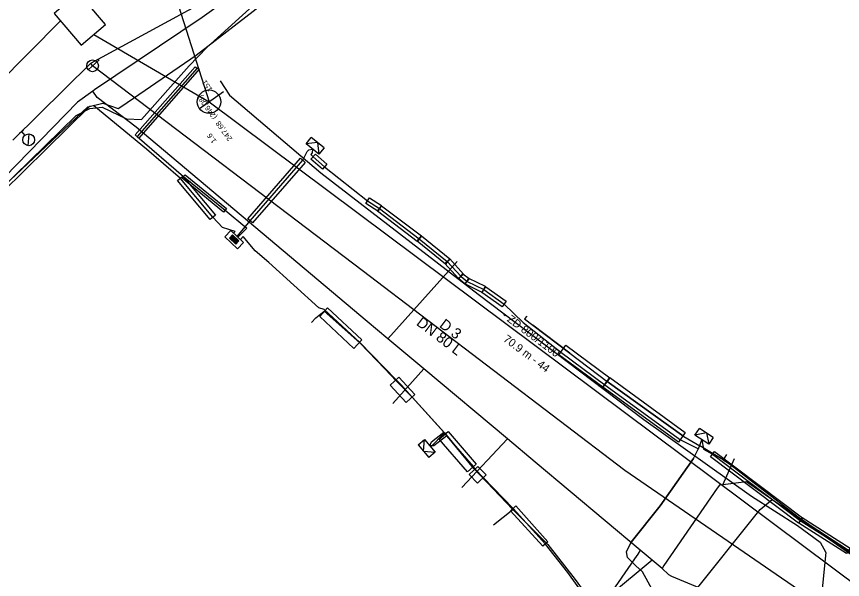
# Model space of a CAD drawing. Extents: x -600636 to -600148, y -1203980 to -1203569.
# Drawn here: x -600384.3 to -600313.9, y -1203678.1 to -1203630.1 of the extents above; entities that cross this region are included whole.
import ezdxf

# ---------------------------------------------------------------- set-up
doc = ezdxf.new("R2010")
doc.units = 0
for name, color, linetype in [('Cetin zam průběh', 7, 'Continuous'), ('EON objekty', 7, 'Continuous'), ('EON podzemní NN', 7, 'Continuous'), ('EON podzemní VN', 7, 'Continuous'), ('GasNet NTL', 7, 'Continuous'), ('Implicitní', 7, 'Continuous'), ('VaK Břeclav_kanalizace', 7, 'Continuous'), ('Vak Břeclav_vodovod', 7, 'Continuous'), ('Vrstva 9', 7, 'Continuous')]:
    doc.layers.add(name, color=color, linetype=linetype)

# ---------------------------------------------------------------- blocks, each defined once
blk = doc.blocks.new('NN630')
at = {"layer": 'Vrstva 9'}
for points in [[(-0.003, -0.7), (-0.703, 0)], [(-0.703, -0.7), (-0.703, 0), (0.697, 0), (0.697, -0.7)], [(-0.703, -0.7), (0.697, -0.7)], [(-0.003, -0.7), (0.697, 0)]]:
    blk.add_lwpolyline(points, dxfattribs=at)
blk = doc.blocks.new('NN620')
at = {"layer": 'EON objekty'}
for points in [[(0.752, 0.004), (-0.748, 0.004)], [(-0.748, 0.004), (-0.748, -0.746)], [(0.752, -0.746), (0.752, 0.004)], [(0.368, -0.18), (-0.376, -0.18)], [(-0.376, -0.18), (-0.376, -0.558)], [(-0.376, -0.558), (0.368, -0.558)], [(0.321, -0.227), (-0.329, -0.227)], [(-0.329, -0.227), (-0.329, -0.51)], [(-0.329, -0.51), (0.321, -0.51)], [(0.274, -0.274), (-0.281, -0.274)], [(-0.281, -0.274), (-0.281, -0.463)], [(-0.281, -0.463), (0.274, -0.463)], [(0.227, -0.321), (-0.234, -0.321)], [(-0.234, -0.321), (-0.234, -0.416)], [(-0.234, -0.416), (0.227, -0.416)], [(-0.193, -0.369), (0.185, -0.369)], [(0.227, -0.416), (0.227, -0.321)], [(0.274, -0.463), (0.274, -0.274)], [(0.321, -0.51), (0.321, -0.227)], [(0.368, -0.558), (0.368, -0.18)], [(-0.748, -0.746), (0.752, -0.746)]]:
    blk.add_lwpolyline(points, dxfattribs=at)
blk = doc.blocks.new('MoSymbol 2')
at = {"layer": 'Implicitní'}
blk.add_line((0, 0.0005), (0, -0.00075), dxfattribs=at)
blk.add_circle((0, 0), 0.0005, dxfattribs=at)
blk = doc.blocks.new('MoSymbol 3')
at = {"layer": 'Implicitní'}
for p, q in [((-0.000225, 0.00095), (0.000225, 0.00095)), ((0, 0.00095), (0, 0.0005)), ((-0.000365, -0.000365), (0.000365, 0.000365))]:
    blk.add_line(p, q, dxfattribs=at)
blk.add_circle((0, 0), 0.0005, dxfattribs=at)

msp = doc.modelspace()

# ---------------------------------------------------------------- linework, layer by layer
at = {"layer": 'Cetin zam průběh'}
for points in [[(-600403.75, -1203662.4), (-600400.59, -1203659.29), (-600391.04, -1203649.83), (-600378.25, -1203637.79), (-600376.97, -1203637.47), (-600375.66, -1203637.95), (-600375.36, -1203637.74), (-600369.01, -1203633.38), (-600361.52, -1203627.61), (-600348.82, -1203618.06), (-600335.53, -1203608.82), (-600318.11, -1203596.27), (-600313.64, -1203592.14)], [(-600368.09, -1203632.74), (-600363.25, -1203628.32)], [(-600385.87, -1203644.99), (-600379.24, -1203638.53), (-600378.07, -1203637.95), (-600377.04, -1203637.82), (-600374.96, -1203638.83), (-600373.66, -1203638.86), (-600369.62, -1203634.3), (-600368.09, -1203632.74)], [(-600375.36, -1203637.74), (-600369.01, -1203633.38)], [(-600373.66, -1203638.86), (-600369.62, -1203634.3)], [(-600359.16, -1203656.16), (-600358.81, -1203655.77), (-600358.09, -1203655.2), (-600355.04, -1203657.89), (-600352.93, -1203660.11), (-600351.96, -1203661.13), (-600350.57, -1203662.57), (-600347.84, -1203665.57)], [(-600358.09, -1203655.2), (-600355.04, -1203657.89)], [(-600340.82, -1203655.62), (-600341, -1203655.85), (-600340.3, -1203656.39), (-600337.13, -1203658.78), (-600333.94, -1203661.19), (-600327.42, -1203665.89), (-600326.06, -1203666.68)], [(-600337.13, -1203658.78), (-600340.3, -1203656.39)], [(-600351.96, -1203661.13), (-600350.57, -1203662.57)], [(-600327.42, -1203665.89), (-600333.94, -1203661.19)], [(-600349.03, -1203666.79), (-600347.84, -1203665.57)], [(-600347.84, -1203665.57), (-600345.32, -1203668.62)], [(-600341.99, -1203672.1), (-600345.32, -1203668.62), (-600347.84, -1203665.57)], [(-600331.52, -1203676.9), (-600332.22, -1203676.19), (-600332.3, -1203675.71), (-600331.92, -1203674.9), (-600329.44, -1203671.78), (-600326.6, -1203667.76), (-600326.06, -1203666.68)], [(-600324.05, -1203667.87), (-600326.06, -1203666.68)], [(-600323.77, -1203667.42), (-600324.05, -1203667.87)], [(-600326.6, -1203667.76), (-600329.44, -1203671.78), (-600331.92, -1203674.9)], [(-600324.05, -1203667.87), (-600323.52, -1203668.21), (-600317.28, -1203673.02), (-600311.48, -1203676.78)], [(-600323.52, -1203668.21), (-600317.28, -1203673.02)], [(-600329.02, -1203689.27), (-600327.65, -1203686.16), (-600327.07, -1203683.69), (-600326.94, -1203681.95), (-600327.13, -1203680.22), (-600326.9, -1203679.6), (-600320.9, -1203672.11), (-600319.87, -1203671.25), (-600312.14, -1203676.45), (-600307.68, -1203679.27), (-600299.7, -1203684.11), (-600292.77, -1203688.32), (-600284.45, -1203693.32), (-600273.46, -1203699.98), (-600262.73, -1203706.4), (-600257.97, -1203709.2), (-600243.31, -1203717.93), (-600240.56, -1203720.13), (-600238.73, -1203718.32)], [(-600343.64, -1203673.42), (-600341.99, -1203672.1)], [(-600341.99, -1203672.1), (-600339.02, -1203675.1)], [(-600341.99, -1203672.1), (-600339.02, -1203675.1), (-600336.67, -1203678.06), (-600335.49, -1203679.73), (-600334.6, -1203680.94), (-600332.38, -1203684.29), (-600330.34, -1203687.27), (-600329.66, -1203687.89)], [(-600329.66, -1203687.89), (-600329.92, -1203686.15), (-600329.28, -1203683.93), (-600328.92, -1203681.87), (-600329, -1203680.95), (-600330.94, -1203677.41), (-600331.52, -1203676.9)]]:
    msp.add_lwpolyline(points, dxfattribs=at)
at = {"layer": 'EON podzemní NN'}
for points in [[(-600369.107, -1203634.396), (-600368.748, -1203634.595), (-600368.748, -1203634.595), (-600373.899, -1203640.453), (-600374.2, -1203640.188)], [(-600359.216, -1203642.251), (-600358.833, -1203641.82), (-600357.859, -1203642.686), (-600358.243, -1203643.117)], [(-600360.118, -1203642.173), (-600359.712, -1203642.525), (-600364.197, -1203647.69), (-600364.6, -1203647.341)], [(-600370.59, -1203644.082), (-600370.152, -1203643.715), (-600367.372, -1203647.024), (-600367.812, -1203647.394)], [(-600369.954, -1203643.575), (-600366.423, -1203646.455), (-600366.676, -1203646.765), (-600370.207, -1203643.885)], [(-600354.533, -1203646.022), (-600354.217, -1203645.538), (-600353.207, -1203646.198), (-600353.522, -1203646.681)], [(-600353.548, -1203646.691), (-600353.191, -1203646.221), (-600349.803, -1203648.791), (-600350.16, -1203649.261)], [(-600350.151, -1203649.253), (-600349.786, -1203648.798), (-600347.372, -1203650.733), (-600347.738, -1203651.189)], [(-600347.794, -1203651.139), (-600347.366, -1203650.751), (-600346.195, -1203652.04), (-600346.624, -1203652.43)], [(-600346.606, -1203652.464), (-600346.257, -1203652.011), (-600345.732, -1203652.415), (-600346.082, -1203652.868)], [(-600346.042, -1203652.91), (-600345.786, -1203652.388), (-600344.357, -1203653.089), (-600344.612, -1203653.61)], [(-600344.638, -1203653.601), (-600344.306, -1203653.13), (-600342.564, -1203654.357), (-600342.896, -1203654.828)], [(-600358.474, -1203655.658), (-600357.794, -1203654.927), (-600354.871, -1203657.644), (-600355.553, -1203658.376)], [(-600338.073, -1203658.917), (-600337.478, -1203658.113), (-600333.74, -1203660.889), (-600334.333, -1203661.688)], [(-600351.089, -1203662.981), (-600352.449, -1203661.51), (-600351.713, -1203660.831), (-600350.355, -1203662.302)], [(-600334.326, -1203661.687), (-600333.733, -1203660.87), (-600327.293, -1203665.553), (-600327.881, -1203666.362)], [(-600348.277, -1203666.113), (-600347.521, -1203665.458), (-600345.117, -1203668.235), (-600345.873, -1203668.89)], [(-600325.136, -1203667.608), (-600324.793, -1203667.153), (-600317.304, -1203672.819), (-600317.64, -1203673.263)], [(-600345.716, -1203669.119), (-600344.993, -1203668.428), (-600344.288, -1203669.165), (-600345.011, -1203669.856)], [(-600342.193, -1203672.206), (-600341.753, -1203671.806), (-600339.003, -1203674.851), (-600339.437, -1203675.243)], [(-600317.616, -1203673.271), (-600317.317, -1203672.8), (-600313.236, -1203675.395), (-600313.532, -1203675.861)]]:
    msp.add_lwpolyline(points, close=True, dxfattribs=at)
for points in [[(-600368.927, -1203634.495), (-600374.05, -1203640.32), (-600370.08, -1203643.73), (-600366.55, -1203646.61), (-600364.68, -1203648.12), (-600365.448, -1203648.9)], [(-600365.812, -1203648.565), (-600365.681, -1203648.403), (-600366.76, -1203648.07), (-600367.58, -1203647.21), (-600370.36, -1203643.9), (-600373.24, -1203641.39), (-600377.75, -1203637.7), (-600378.11, -1203637.77), (-600385.513, -1203645.048)], [(-600365.519, -1203648.839), (-600364.39, -1203647.52), (-600359.91, -1203642.35), (-600359.54, -1203641.598), (-600359.414, -1203641.455), (-600359.09, -1203641.39), (-600359.12, -1203641.727), (-600359.24, -1203641.863), (-600359.03, -1203642.05), (-600358.06, -1203642.92), (-600354.39, -1203645.79), (-600353.38, -1203646.45), (-600350, -1203649.03), (-600347.59, -1203650.97), (-600346.42, -1203652.26), (-600345.9, -1203652.67), (-600344.47, -1203653.37), (-600342.73, -1203654.6), (-600341.114, -1203656.177), (-600337.892, -1203658.699), (-600334.149, -1203661.481), (-600327.695, -1203666.161), (-600326.17, -1203666.939), (-600325.88, -1203666.16), (-600325.749, -1203666.954), (-600324.98, -1203667.4), (-600317.48, -1203673.05), (-600313.39, -1203675.63)], [(-600334.77, -1203681), (-600337.32, -1203677.47), (-600339.22, -1203675.06), (-600341.977, -1203672.021), (-600344.526, -1203669.391), (-600345.213, -1203668.675), (-600345.36, -1203668.449), (-600347.63, -1203665.83), (-600348.726, -1203666.671), (-600349.08, -1203666.69), (-600348.944, -1203666.334), (-600347.896, -1203665.529), (-600350.6, -1203662.52), (-600351.494, -1203661.523), (-600351.96, -1203661.043), (-600355.061, -1203657.866), (-600358.09, -1203655.066), (-600358.55, -1203654.911), (-600362.8, -1203651.07), (-600363.99, -1203650.06), (-600365.009, -1203648.842), (-600365.226, -1203649.112)]]:
    msp.add_lwpolyline(points, dxfattribs=at)
at = {"layer": 'EON podzemní VN'}
msp.add_lwpolyline([(-600366.95, -1203635.593), (-600366.181, -1203636.795), (-600358.381, -1203643.411), (-600344.954, -1203653.759), (-600330.827, -1203664.425), (-600321.645, -1203670.963), (-600317.713, -1203673.458), (-600315.791, -1203674.896), (-600315.293, -1203675.777), (-600315.944, -1203682.246), (-600316.226, -1203683.581), (-600322.501, -1203693.042), (-600331.079, -1203704.985), (-600348.911, -1203730.288), (-600354.208, -1203737.743), (-600361.516, -1203748.136), (-600365.138, -1203753.003), (-600368.824, -1203758.254), (-600375.091, -1203769.039), (-600381.398, -1203780.278), (-600382.49, -1203782.6), (-600383.25, -1203783.59)], dxfattribs=at)
at = {"layer": 'GasNet NTL'}
for points in [[(-600363.908, -1203626.786), (-600366.43, -1203628.72), (-600368.49, -1203630.18), (-600377.69, -1203636.35), (-600377.83, -1203636.45), (-600379.12, -1203637.4), (-600390.52, -1203649.08), (-600393.75, -1203652.39), (-600407.12, -1203666.06), (-600410.69, -1203669.71), (-600416.55, -1203675.06), (-600425.93, -1203683.63), (-600443.216, -1203700.032), (-600443.404, -1203700.211), (-600447.923, -1203704.499), (-600448.05, -1203704.619)], [(-600329.27, -1203677.14), (-600330.12, -1203676.43), (-600331.14, -1203675.57), (-600340.09, -1203668.06), (-600342.45, -1203666.09), (-600349.58, -1203660.13), (-600352.66, -1203657.56), (-600354.43, -1203656.08), (-600374.14, -1203639.53), (-600377.45, -1203637.01), (-600377.83, -1203636.45)], [(-600352.66, -1203657.56), (-600346.75, -1203650.97)], [(-600352.23, -1203663.07), (-600349.58, -1203660.13)], [(-600346.34, -1203670.24), (-600342.45, -1203666.09)], [(-600324.1, -1203669.99), (-600323.1, -1203667.75)], [(-600309.24, -1203678.67), (-600322.08, -1203669.74), (-600324.1, -1203669.99), (-600324.38, -1203670.02), (-600324.57, -1203670.3), (-600329.11, -1203676.87), (-600329.27, -1203677.14), (-600328.72, -1203677.64), (-600328.46, -1203677.78), (-600313.71, -1203683.92)], [(-600331.14, -1203675.57), (-600331.35, -1203675.9), (-600331.63, -1203676.31)], [(-600331.63, -1203676.31), (-600333.84, -1203679.52), (-600334.07, -1203679.86), (-600334.63, -1203680.67), (-600332.29, -1203684.08), (-600331.07, -1203685.85), (-600329.31, -1203687.34), (-600321.69, -1203692.03)], [(-600330.12, -1203676.43), (-600333.84, -1203679.52), (-600334.14, -1203679.77)]]:
    msp.add_lwpolyline(points, dxfattribs=at)
at = {"layer": 'VaK Břeclav_kanalizace'}
for p, q in [((-600373.126, -1203620.905), (-600367.912, -1203637.359)), ((-600421.971, -1203671.963), (-600380.571, -1203630.481)), ((-600377.747, -1203631.629), (-600367.912, -1203637.359)), ((-600367.912, -1203637.359), (-600311.102, -1203679.776))]:
    msp.add_line(p, q, dxfattribs=at)
msp.add_lwpolyline([(-600380.107, -1203626.821), (-600381.1, -1203627.66), (-600380.127, -1203628.993), (-600381.12, -1203629.832), (-600378.829, -1203632.544), (-600376.754, -1203630.791)], close=True, dxfattribs=at)
at = {"layer": 'Vak Břeclav_vodovod'}
for p, q in [((-600377.983, -1203634.082), (-600365.168, -1203627.107)), ((-600384.65, -1203640.632), (-600377.983, -1203634.082)), ((-600377.846, -1203634.299), (-600377.983, -1203634.082))]:
    msp.add_line(p, q, dxfattribs=at)
msp.add_lwpolyline([(-600316.256, -1203679.894), (-600332.434, -1203668.792), (-600354.837, -1203651.734), (-600377.846, -1203634.299)], dxfattribs=at)

# ---------------------------------------------------------------- block references
at = {"layer": 'EON podzemní NN'}
for name, p, rotation in [('NN630', (-600359.09, -1203641.39), 141.80983611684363), ('NN620', (-600365.52, -1203648.84), -42.98922773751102), ('NN630', (-600325.88, -1203666.16), 146.63981950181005), ('NN630', (-600349.08, -1203666.69), -50.01474170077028)]:
    msp.add_blockref(name, p, dxfattribs=dict(at, rotation=rotation))
at = {"layer": 'VaK Břeclav_kanalizace', "xscale": 1999.750031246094, "yscale": 1999.7500312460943, "rotation": 125.4179044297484}
msp.add_blockref('MoSymbol 2', (-600367.912, -1203637.359), dxfattribs=at)
at = {"layer": 'Vak Břeclav_vodovod', "xscale": 999.875015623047}
for name, p, yscale, rotation in [('MoSymbol 2', (-600377.846, -1203634.299), 999.875015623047, 132.556395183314), ('MoSymbol 3', (-600383.292, -1203640.604), 999.8750156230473, 41.15293018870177)]:
    msp.add_blockref(name, p, dxfattribs=dict(at, yscale=yscale, rotation=rotation))

# ---------------------------------------------------------------- texts
at = {"layer": 'VaK Břeclav_kanalizace'}
for s, height, rotation, p in [('151', 0.4549, 125.4179, (-600367.592, -1203636.309)), ('247,68  (246,08)', 0.45494, 125.4179, (-600365.897, -1203640.508)), ('1.6', 0.4549, 125.4179, (-600367.246, -1203640.71)), ('- ZD 800/1100', 0.68241, 323.25327, (-600342.996, -1203655.68)), ('70.9 m - 44', 0.68241, 323.25327, (-600342.871, -1203657.708))]:
    msp.add_text(s, height=height, rotation=rotation, dxfattribs=at).set_placement(p)
at = {"layer": 'Vak Břeclav_vodovod'}
for s, p in [('DN 80 L', (-600350.296, -1203656.335)), ('D 3', (-600348.331, -1203656.511))]:
    msp.add_text(s, height=0.9099, rotation=322.71378, dxfattribs=at).set_placement(p)

doc.saveas('drawing.dxf')
